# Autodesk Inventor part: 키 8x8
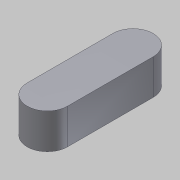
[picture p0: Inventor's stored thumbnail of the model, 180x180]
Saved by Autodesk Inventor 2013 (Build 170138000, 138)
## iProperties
Company: 한국ATC센터
Created: 2014-10
Part Number: 키 8x8
Document SubType Name: Modeling
Designer: 한국ATC센터
Density: 7.86 g/cm^3
Material: 강철, 연강
Mass: 10.2483 g
Surface Area: 7.8646 cm^2
Volume: 1.30386 cm^3
Author: KYOUNG IL JANG
Revision Number: 1
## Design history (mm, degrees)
sketch "스케치1"
  geometry: L1 (28.264, -14)-(28.264, -31) reference; L2 (20.264, -31)-(20.264, -14) reference; A1 r 4 centre (24.264, -31) between (20.264, -31) and (28.264, -31) reference; A2 r 4 centre (24.264, -14) between (28.264, -14) and (20.264, -14) reference; 1 further point
extrude "돌출1" new body sketch "스케치1" distance "d0" = 7; taper "d1" = 0 deg
node "솔리드1"
node "참조1"
